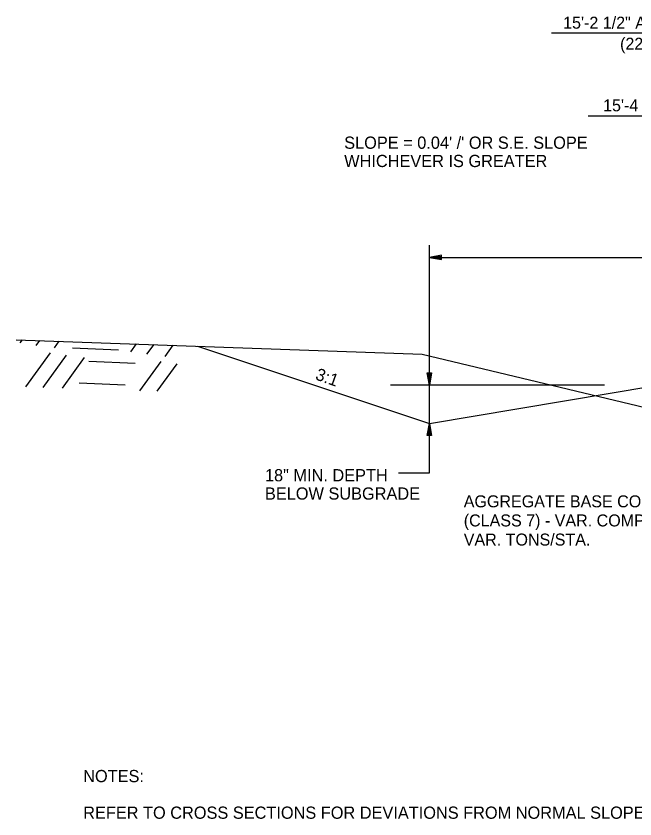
# Model space of a CAD drawing. Extents: x 1461846 to 1462006, y 1686171 to 1686805.
# Drawn here: x 1461847.36 to 1461877.78, y 1686329.7 to 1686369.19 of the extents above; entities that cross this region are included whole.
import ezdxf

# ---------------------------------------------------------------- set-up
doc = ezdxf.new("R2010")
doc.units = 0
for name, color, linetype in [('19', 7, 'Continuous'), ('20', 7, 'Continuous'), ('42', 7, 'Continuous'), ('R_Draft', 7, 'Continuous')]:
    doc.layers.add(name, color=color, linetype=linetype)

msp = doc.modelspace()

# ---------------------------------------------------------------- linework, layer by layer
at = {"layer": '19'}
for p, q in [((1461847.563, 1686353.112), (1461847.674, 1686353.258)), ((1461848.354, 1686352.992), (1461848.529, 1686353.23)), ((1461849.246, 1686352.868), (1461849.483, 1686353.198)), ((1461850.134, 1686352.866), (1461852.393, 1686352.775)), ((1461853.005, 1686352.679), (1461853.281, 1686353.065)), ((1461853.796, 1686352.56), (1461854.145, 1686353.036)), ((1461854.688, 1686352.436), (1461855.089, 1686352.996)), ((1461847.839, 1686350.953), (1461849.051, 1686352.632)), ((1461848.693, 1686350.925), (1461849.843, 1686352.513)), ((1461849.648, 1686350.894), (1461850.734, 1686352.389)), ((1461850.941, 1686352.209), (1461853.21, 1686352.116)), ((1461853.446, 1686350.761), (1461854.494, 1686352.2)), ((1461854.3, 1686350.733), (1461855.285, 1686352.08)), ((1461850.462, 1686351.155), (1461852.719, 1686351.053))]:
    msp.add_line(p, q, dxfattribs=at)
at = {"layer": '20'}
for p, q in [((1461897.555, 1686368.339), (1461873.688, 1686368.339)), ((1461897.419, 1686364.27), (1461875.488, 1686364.27))]:
    msp.add_line(p, q, dxfattribs=at)
at = {"layer": 'R_Draft'}
for p, q in [((1461867.68, 1686350.99), (1461867.68, 1686357.918)), ((1461868.28, 1686357.423), (1461867.68, 1686357.318)), ((1461867.68, 1686357.318), (1461897.68, 1686357.318)), ((1461867.68, 1686357.318), (1461868.28, 1686357.213)), ((1461868.28, 1686357.368), (1461867.84, 1686357.333)), ((1461867.84, 1686357.303), (1461868.28, 1686357.263)), ((1461868.28, 1686357.213), (1461868.28, 1686357.423)), ((1461856.288, 1686352.954), (1461867.68, 1686349.156)), ((1461867.68, 1686349.156), (1461889.68, 1686352.823)), ((1461867.575, 1686351.633), (1461867.785, 1686351.633)), ((1461867.68, 1686351.033), (1461867.575, 1686351.633)), ((1461867.665, 1686351.193), (1461867.63, 1686351.633)), ((1461867.785, 1686351.633), (1461867.68, 1686351.033)), ((1461867.735, 1686351.633), (1461867.695, 1686351.193)), ((1461876.286, 1686351.033), (1461865.771, 1686351.033)), ((1461867.68, 1686346.72), (1461867.68, 1686350.99)), ((1461867.575, 1686348.556), (1461867.68, 1686349.156)), ((1461867.625, 1686348.556), (1461867.665, 1686348.996)), ((1461867.68, 1686349.156), (1461867.785, 1686348.556)), ((1461867.695, 1686348.996), (1461867.73, 1686348.556)), ((1461867.785, 1686348.556), (1461867.575, 1686348.556)), ((1461866.164, 1686346.72), (1461867.68, 1686346.72))]:
    msp.add_line(p, q, dxfattribs=at)
msp.add_lwpolyline([(1461847.362, 1686353.269), (1461867.322, 1686352.565), (1461882.06, 1686349.033), (1461884.194, 1686348.879), (1461888.604, 1686349.011), (1461896.486, 1686349.242), (1461912.763, 1686353.534), (1461918.661, 1686353.486), (1461934.122, 1686354.079), (1461940.18, 1686354.549), (1461946.68, 1686353.887), (1461962.552, 1686349.481)], dxfattribs=at)

# ---------------------------------------------------------------- texts
at = {"layer": '19'}
for s, p in [('AGGREGATE BASE COURSE', (1461869.369, 1686345.026)), ('(CLASS 7) - VAR. COMPACTED DEPTH', (1461869.369, 1686344.086)), ('VAR. TONS/STA.', (1461869.369, 1686343.146))]:
    msp.add_text(s, height=0.59001, dxfattribs=at).set_placement(p)
at = {"layer": '42'}
for s, p in [('15\'-2 1/2" AVG. ACHM SURFACE COURSE (1/2")', (1461874.254, 1686368.564)), ('(220 LB./SQ.YD.) & TACK COAT', (1461877.053, 1686367.531)), ('15\'-4 1/8" AVG. ACHM BINDER COURSE (1")', (1461876.219, 1686364.5))]:
    msp.add_text(s, height=0.59001, dxfattribs=at).set_placement(p)
at = {"layer": 'R_Draft'}
for s, p in [("SLOPE = 0.04' /' OR S.E. SLOPE", (1461863.492, 1686362.659)), ('WHICHEVER IS GREATER', (1461863.492, 1686361.759)), ('18" MIN. DEPTH', (1461859.597, 1686346.305)), ('BELOW SUBGRADE', (1461859.597, 1686345.405)), ('NOTES:', (1461850.662, 1686331.511)), ('REFER TO CROSS SECTIONS FOR DEVIATIONS FROM NORMAL SLOPES. NO CHANGES SHALL BE MADE FROM THE ', (1461850.662, 1686329.711))]:
    msp.add_text(s, height=0.6, dxfattribs=at).set_placement(p)
msp.add_text('3:1', height=0.6, rotation=340.4943, dxfattribs=at).set_placement((1461862.035, 1686351.327))

doc.saveas('drawing.dxf')
